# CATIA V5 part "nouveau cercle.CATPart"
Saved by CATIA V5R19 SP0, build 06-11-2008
Part number: Part4
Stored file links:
  F:\20\nouveau cercle.CATPart

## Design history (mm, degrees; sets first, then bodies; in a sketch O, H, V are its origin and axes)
Body1 (main body)
  Sketch1 on yz-plane, origin (0, 0, 0), H (0, 1, 0), V (0, 0, 1)
    circle A1 centre (0, 0) radius 35
    point P1 (0, 35)
    point P2 (35, 0)
    point P3 (0, -35)
    point P4 (-35, 0)
    point P5 (-24.7487, 24.7487)
    point P6 (24.7487, -24.7487)
    point P7 (24.7487, 24.7487)
    point P8 (-24.7487, -24.7487)
    radius A1 = 35
    coincidence: P1 A1, P1 V, P2 A1, P2 H, P3 A1, P3 V, P4 A1, P4 H, P5 A1, P6 A1, P7 A1, P8 A1
    equidistance: P2 P1 P7, P4 P1 P5, P2 P3 P6, P3 P4 P8
  Plane1: type 1Curve, Element1 Sketch1.A1
  Point1: type Center, Curve Sketch1.A1
  Line1: type Normal, RefSkin Plane1, Start 0, End 20, RefPoint Point1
